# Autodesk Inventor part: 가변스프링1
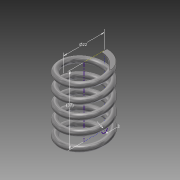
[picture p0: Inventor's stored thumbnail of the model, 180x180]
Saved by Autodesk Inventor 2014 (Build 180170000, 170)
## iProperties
Created: 2015-02
Part Number: 가변스프링1
Material: 강철, 탄소
Document SubType Name: Modeling
Designer: basic
Density: 7.87 g/cm^3
Appearance: 반연마
Mass: 18.9154 g
Surface Area: 32.5802 cm^2
Volume: 2.40348 cm^3
Author: basic
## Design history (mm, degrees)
sketch "스케치1"
  geometry: L1 (0, 0)-(11, 0); L2 (11, 0)-(11, 25.358); L3 (11, 25.358)-(0, 25.358); L4 (0, 25.358)-(0, 0); C1 r 1.5 at (11, 0)
  constraints: 8 end point, 2 parallel, 1 centre point, 1 coincident, 1 horizontal, 1 perpendicular
  dimensions: "d0" = 22 diameter of L2 L4; "d1" = 25.3583 distance of L3.end L1.start (derived); "d2" = 3 diameter of C1
feature "코일1" sketch "스케치1" pitch "d3" = 10; turns "d5" = 5; dims "d4" = 25.3583 (= d1), "d6" = 0, angle "d7" = 90 deg, angle "d8" = 90 deg, "d9" = 0, "d10" = 0
sketch "스케치2"
  geometry: L1 (0, 12.5)-(0, 9.5) reference; L2 (0, 12.5)-(0, 9.5) reference; 1 further point
  constraints: 2 vertical alignment
extrude "돌출1" cut sketch "스케치2" stored distance "d11" = 10; taper "d12" = 0 deg
node "작업 평면1"
sketch "스케치3"
  geometry: L1 (1.5, 0)-(-1.5, 0) reference; 1 further point
  constraints: 1 horizontal alignment
extrude "돌출2" cut sketch "스케치3" stored distance "d14" = 10; taper "d15" = 0 deg
node "솔리드1"
node "절단 모서리 투영1"
node "절단 모서리 투영2"
node "절단 모서리 투영3"
other parameters: "d13" = 0
